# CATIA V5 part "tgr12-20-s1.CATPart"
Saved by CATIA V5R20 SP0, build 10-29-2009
Part number: TGR12-20-S1
Revision: 1
Definition: design
Nomenclature: TGR12-20-S1
Source: made
Description: NOT SPECIFIED
Bounding box of the stored display mesh (mm): x -22 to 0.8, y 0 to 12, z -6 to 6
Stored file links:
  C:\Users\Raffaele\Desktop\3D X SITO CF\I-MOLD\TGR-S1\tgr12-s1.step\tgr12-20-s1.CATPart
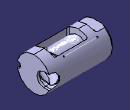
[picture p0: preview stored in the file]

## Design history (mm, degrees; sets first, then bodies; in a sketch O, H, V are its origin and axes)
Set1
  Line1 "LINE #4369": stored without definition
  DatumCurve1 "COMPOSITE_CURVE #4424"
  DatumCurve2 "COMPOSITE_CURVE #4473"
  DatumCurve3 "COMPOSITE_CURVE #4552"
  DatumCurve4 "COMPOSITE_CURVE #4595"
  DatumCurve5 "COMPOSITE_CURVE #4824"
  DatumCurve6 "COMPOSITE_CURVE #4965"
  DatumCurve7 "COMPOSITE_CURVE #4992"
  DatumCurve8 "COMPOSITE_CURVE #5050"
  DatumCurve9 "COMPOSITE_CURVE #5107"
  DatumCurve10 "COMPOSITE_CURVE #5136"
  DatumSurface1 "OPEN_SHELL #4359"
Body1 "MANIFOLD_SOLID_BREP #4360" (main body)
  Solid1: solid without history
